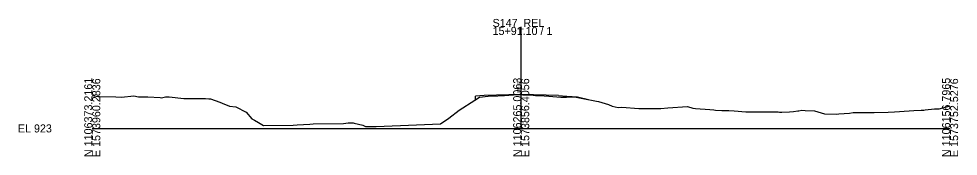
# Model space of a CAD drawing. Extents: x 1557985 to 1558314, y 1113650 to 1118205.
# Drawn here: x 1557985.4 to 1558314, y 1113650.1 to 1113698.1 of the extents above; entities that cross this region are included whole.
import ezdxf

# ---------------------------------------------------------------- set-up
doc = ezdxf.new("R2010")
doc.units = 0
for name, color, linetype in [('RD_GPK_XS_Cell', 7, 'Continuous'), ('RD_XS_EarthShd', 7, 'Continuous'), ('RD_XS_ExGround', 7, 'Continuous'), ('RD_XS_Pave', 7, 'Continuous'), ('RD_XS_TieSlope', 7, 'Continuous'), ('RD_XS_TX_Elev_EX', 7, 'Continuous')]:
    doc.layers.add(name, color=color, linetype=linetype)

msp = doc.modelspace()

# ---------------------------------------------------------------- linework, layer by layer
at = {"layer": 'RD_GPK_XS_Cell'}
for p, q in [((1558161.13, 1113659.8), (1558161.13, 1113695.23)), ((1558011.13, 1113659.8), (1558161.13, 1113659.8)), ((1558161.13, 1113659.8), (1558311.13, 1113659.8))]:
    msp.add_line(p, q, dxfattribs=at)
at = {"layer": 'RD_XS_EarthShd'}
for p, q in [((1558148.13, 1113671.33), (1558145.13, 1113671.09)), ((1558174.13, 1113671.33), (1558177.13, 1113671.09)), ((1558177.13, 1113671.09), (1558180.88, 1113670.79))]:
    msp.add_line(p, q, dxfattribs=at)
at = {"layer": 'RD_XS_ExGround'}
msp.add_lwpolyline([(1558011.13, 1113671.33), (1558011.85, 1113671.18), (1558013.23, 1113670.95), (1558013.63, 1113670.89), (1558019.41, 1113670.78), (1558021.3, 1113670.66), (1558025.64, 1113671.15), (1558027.26, 1113670.82), (1558030.55, 1113670.83), (1558034.9, 1113670.57), (1558035.36, 1113670.53), (1558036.77, 1113670.81), (1558038.02, 1113670.78), (1558043.15, 1113670.24), (1558050.75, 1113670.19), (1558051.94, 1113670.17), (1558052.48, 1113670.12), (1558055.74, 1113668.98), (1558056.61, 1113668.67), (1558059.1, 1113667.59), (1558061.32, 1113667.38), (1558064.95, 1113665.43), (1558066.97, 1113663.2), (1558067.82, 1113662.66), (1558069.25, 1113661.9), (1558071, 1113660.81), (1558081.39, 1113660.92), (1558082.73, 1113661.07), (1558087.18, 1113661.27), (1558088.34, 1113661.36), (1558099.01, 1113661.51), (1558100.65, 1113661.77), (1558102.36, 1113661.72), (1558102.73, 1113661.66), (1558105.74, 1113660.89), (1558106.65, 1113660.42), (1558110.39, 1113660.44), (1558124.52, 1113661.02), (1558132.96, 1113661.36), (1558135.79, 1113663.41), (1558139.45, 1113666.21), (1558144.93, 1113669.61), (1558146.58, 1113670.69), (1558149.61, 1113671.05), (1558153.01, 1113671.13), (1558155.33, 1113671.33), (1558156.8, 1113671.44), (1558160.12, 1113671.61), (1558161.13, 1113671.59), (1558161.65, 1113671.58), (1558162.12, 1113671.56), (1558163.88, 1113671.49), (1558164.37, 1113671.47), (1558166.19, 1113671.35), (1558167.59, 1113671.24), (1558170.82, 1113671.03), (1558175.04, 1113670.7), (1558176.92, 1113670.66), (1558179.78, 1113670.78), (1558182.65, 1113670.22), (1558187.44, 1113669.32), (1558188.12, 1113669.15), (1558191.7, 1113668.16), (1558192.98, 1113667.6), (1558195.04, 1113667.05), (1558196.36, 1113667.19), (1558202.27, 1113666.76), (1558208.81, 1113666.7), (1558209.93, 1113666.76), (1558212.47, 1113667.03), (1558219.25, 1113667.44), (1558221.17, 1113666.87), (1558222.07, 1113666.78), (1558227.16, 1113666.46), (1558228.53, 1113666.27), (1558229.08, 1113666.17), (1558231.35, 1113666.09), (1558233.78, 1113666), (1558235.57, 1113665.89), (1558239.7, 1113665.64), (1558240.47, 1113665.63), (1558242.19, 1113665.56), (1558246.03, 1113665.6), (1558248.76, 1113665.57), (1558251.03, 1113665.54), (1558251.5, 1113665.52), (1558252.32, 1113665.53), (1558254.92, 1113665.55), (1558256.4, 1113665.74), (1558257.83, 1113665.89), (1558258.27, 1113665.98), (1558259.29, 1113666.18), (1558260.48, 1113666.05), (1558263.66, 1113665.98), (1558267.21, 1113664.87), (1558271.53, 1113664.78), (1558272.26, 1113664.84), (1558275.98, 1113665.18), (1558277.21, 1113665.32), (1558278.29, 1113665.4), (1558280.05, 1113665.35), (1558281.77, 1113665.35), (1558283.13, 1113665.32), (1558284.13, 1113665.3), (1558284.63, 1113665.33), (1558289.5, 1113665.43), (1558291.65, 1113665.57), (1558296.82, 1113665.93), (1558298.4, 1113666), (1558301.04, 1113666.16), (1558301.93, 1113666.22), (1558302.44, 1113666.27), (1558305.66, 1113666.61), (1558307.28, 1113666.67), (1558311.13, 1113667.7)], dxfattribs=at)
at = {"layer": 'RD_XS_Pave'}
for p, q in [((1558161.13, 1113671.59), (1558148.13, 1113671.33)), ((1558174.13, 1113671.33), (1558161.13, 1113671.59))]:
    msp.add_line(p, q, dxfattribs=at)
at = {"layer": 'RD_XS_TieSlope'}
for p, q in [((1558145.13, 1113669.74), (1558145.13, 1113671.09)), ((1558180.88, 1113670.79), (1558184.69, 1113669.84))]:
    msp.add_line(p, q, dxfattribs=at)

# ---------------------------------------------------------------- texts
at = {"layer": 'RD_GPK_XS_Cell'}
for s, p in [('S147_REL', (1558151.13, 1113695.23)), ('15+91.10 / 1', (1558151.13, 1113692.43)), ('EL 923', (1557985.13, 1113658.4))]:
    msp.add_text(s, height=2.8, dxfattribs=at).set_placement(p)
for s, p in [('N 1106373.2161', (1558011.13, 1113649.8)), ('E 1573960.2836', (1558013.93, 1113649.8)), ('N 1106265.0063', (1558161.13, 1113649.8)), ('E 1573856.4056', (1558163.93, 1113649.8)), ('N 1106156.7965', (1558311.13, 1113649.8)), ('E 1573752.5276', (1558313.93, 1113649.8))]:
    msp.add_text(s, height=2.8, rotation=90, dxfattribs=at).set_placement(p)
at = {"layer": 'RD_XS_TX_Elev_EX'}
msp.add_text('934.80', height=1, rotation=90, dxfattribs=at).set_placement((1558160.63, 1113672.09))

doc.saveas('drawing.dxf')
